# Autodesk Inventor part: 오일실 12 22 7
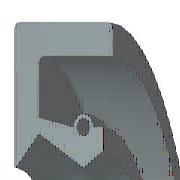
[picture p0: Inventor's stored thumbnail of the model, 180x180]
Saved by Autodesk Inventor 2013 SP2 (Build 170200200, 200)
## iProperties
Created: 2012-02
Part Number: 오일실 12 22 7
Material: 일반
Description: 오일-실
Document SubType Name: Modeling
Standard: KS B 2804
Designer: mduedu
Standards Organization: KS
Language: ko-KR
Size Designation: D - 12 22 7
Categories: <MemberInstance><Categories><Category DisplayName="샤프트 부품" InternalName="7f7aeb1f-a693-4053-b835-cee3144e0d98" Mnemonic="SHFT"><Category DisplayName="실링" Intern
Density: 1 g/cm^3
Mass: 1.3482 g
Surface Area: 18.4996 cm^2
Volume: 1.3482 cm^3
IsCustomPart: 1
Author: mduedu
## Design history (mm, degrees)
revolve "본체" stored, may be unused: angle "d17" = 90 deg
revolve "스프링1" stored, may be unused: angle "d18" = 90 deg
body "Solid1"
sketch "스케치1"
  geometry: L1 (0, 11)-(7, 11); L2 (7, 9.25)-(1.75, 9.25); L3 (1.75, 7.75)-(4.9, 6); L4 (4.9, 6)-(0, 6); L5 (0, 0)-(9.586, 0) reference; L6 (4.9, 6)-(6.3, 6.875); L7 (0, 18)-(0, -3) reference; L8 (-1.941, 0)-(11.507, 0) reference; L9 (4.2, 8.1)-(1.75, 8.59); L10 (1.75, 8.59)-(1.75, 9.25); L11 (0, 11)-(0, 6.088); L12 (4.9, 6)-(0, 6); L13 (1.75, 7.75)-(0.152, 6.028); L14 (7, 11)-(7, 9.25); L15 (5.6, 8.1)-(6.3, 8.1); L16 (6.3, 8.1)-(6.3, 6.875); C1 r 0.455 at (4.9, 8.1); A1 r 0.7 centre (4.9, 8.1) between (5.6, 8.1) and (4.2, 8.1); A2 r 0.088 centre (0.088, 6.088) between (0, 6.088) and (0.152, 6.028); 1 further point
  constraints: 28 end point, 5 horizontal alignment, 5 point on line, 4 point on circle, 4 vertical alignment, 3 centre point, 3 tangent, 2 collinear, 2 horizontal, 2 perpendicular, 1 coincident, 1 parallel
  dimensions: "d0" = 22 diameter of L1 L5 (= SD2); "d1" = 1.75 distance of L1.end L2.start (= SD); "d2" = 0.91 diameter of C1 (= SPDI); "d3" = 1.4 diameter of A1 (= SPDA); "d4" = 12 diameter of L3.end L5 (= NND); "d5" = 15.5 diameter of L3.start L5 (= TKDM); "d7" = 17.18 diameter of L9.end L5 (= TKDM + 0.24 x SWDT); "d8" = 1.75 distance between parallel lines of L11 L10 (= SD); "d9" = 4.9 distance from line of L11 C1.centre (= SPDST); "d10" = 16.2 diameter of C1.centre L5 (= HLDM); "d11" = 0.0875 radius of A2 (= 0.25 x LAB); "d12" = 6.3 distance between parallel lines of L11 L16 (= SDI); "d13" = 13.75 diameter of L6.end L5 (= ABDM); "d14" = 7 distance from line of L11 L1.end (= SWDT)
fillet "모깎기1" dims "d6" = 0.3 (= RR)
other parameters: "SD2" = 22 [user parameter; used in 1 equation term], "SWDT" = 7 [user parameter; used in 2 equation terms], "RR" = 0.3 [user parameter; used in 1 equation term], "SD" = 1.75 [user parameter; used in 2 equation terms], "NND" = 12 [user parameter; used in 1 equation term], "SPDA" = 1.4 [user parameter; used in 1 equation term], "SPDI" = 0.91 [user parameter; used in 1 equation term], "TKDM" = 15.5 [user parameter; used in 2 equation terms], "HLDM" = 16.2 [user parameter; used in 1 equation term], "ABDM" = 13.75 [user parameter; used in 1 equation term], "SDI" = 6.3 [user parameter; used in 1 equation term], "SPDST" = 4.9 [user parameter; used in 1 equation term], "LAB" = 0.35 [user parameter; used in 1 equation term], "d15" = 0, "d16" = 0, "d19" = 0
